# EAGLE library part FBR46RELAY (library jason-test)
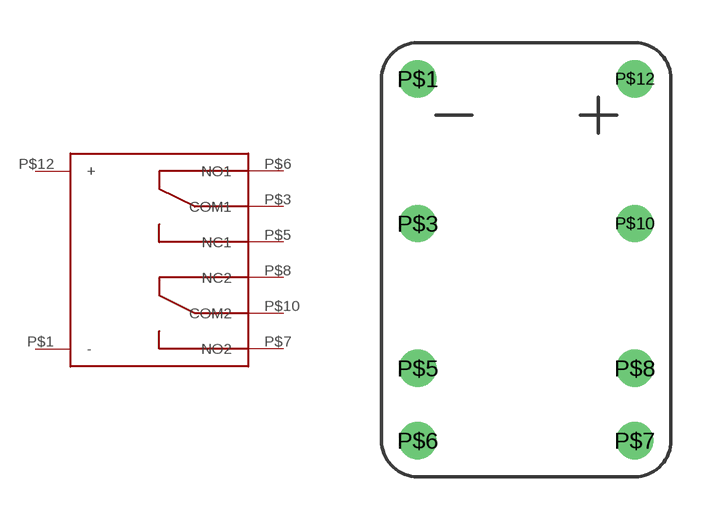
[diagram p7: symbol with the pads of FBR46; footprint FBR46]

Designator prefix -

## FBR46RELAY  [FBR46]
P$1  -
P$3  COM1
P$5  NC1
P$6  NO1
P$7  NO2
P$8  NC2
P$10  COM2
P$12  +

## Footprint FBR46 (pad centres in mm)
FBR46 relay
drill 0.8 round: P$1 0,0; P$3 0,-5.08; P$5 0,-10.16; P$6 0,-12.7; P$7 7.62,-12.7; P$8 7.62,-10.16; P$10 7.62,-5.08; P$12 7.62,0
